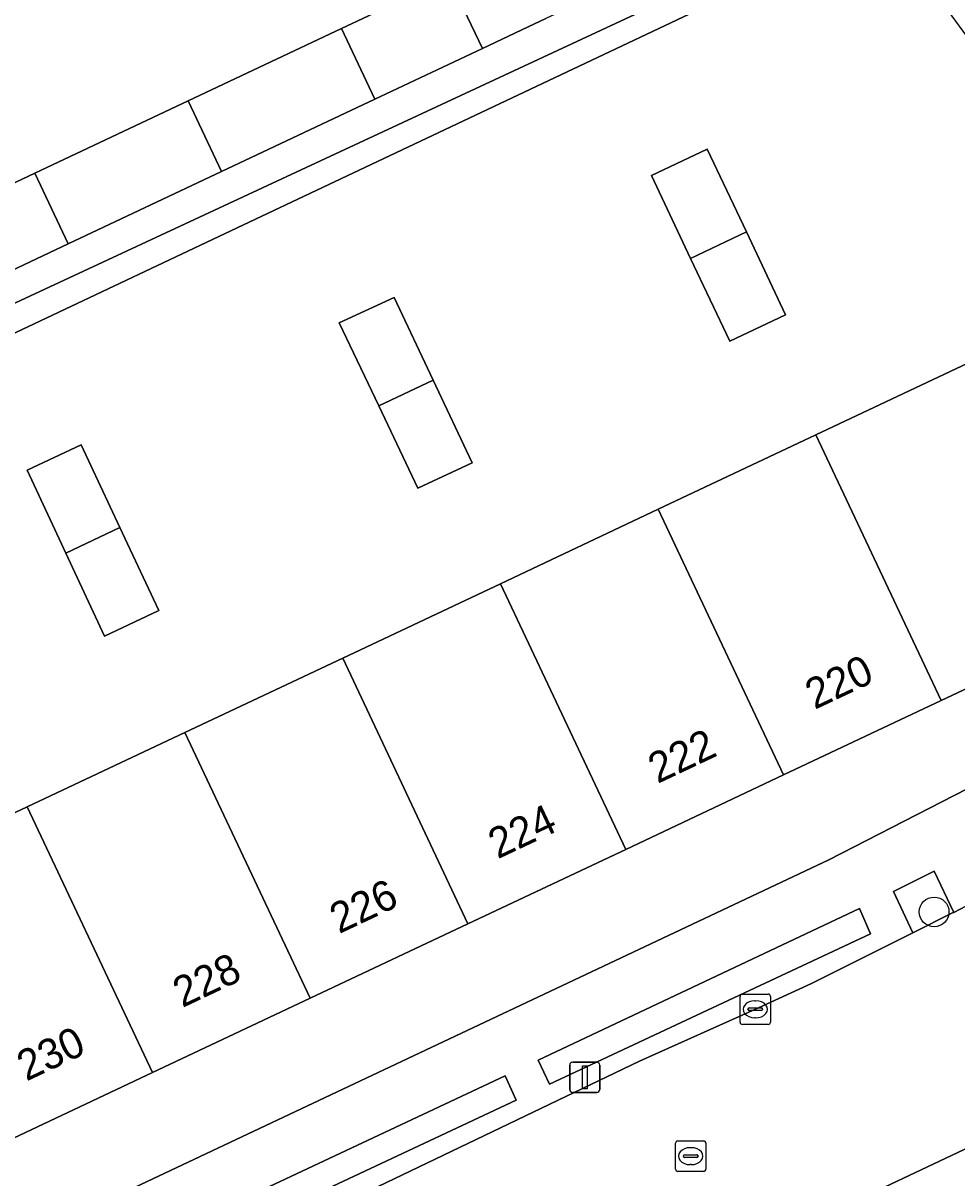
# Model space of a CAD drawing. Extents: x 159039 to 160102, y 381214 to 382524.
# Drawn here: x 159239.29 to 159270.04, y 381343.22 to 381381.25 of the extents above; entities that cross this region are included whole.
import ezdxf

# ---------------------------------------------------------------- set-up
doc = ezdxf.new("R2010")
doc.units = 0
for name, color, linetype in [('IMGEO_Berm_groen', 7, 'Continuous'), ('IMGEO_Boom', 7, 'Continuous'), ('IMGEO_Erf', 7, 'Continuous'), ('IMGEO_Groenvoorziening', 7, 'Continuous'), ('IMGEO_Kolk', 7, 'Continuous'), ('IMGEO_Lichtmast', 7, 'Continuous'), ('IMGEO_Pand', 7, 'Continuous'), ('IMGEO_Pand_nummerreeks', 7, 'Continuous'), ('IMGEO_Rijbaan_lokaal_gesloten', 7, 'Continuous'), ('IMGEO_Rioolput', 7, 'Continuous'), ('IMGEO_Voetpad_open', 7, 'Continuous')]:
    doc.layers.add(name, color=color, linetype=linetype)

msp = doc.modelspace()

# ---------------------------------------------------------------- linework, layer by layer
at = {"layer": 'IMGEO_Berm_groen'}
msp.add_lwpolyline([(159281.002, 381349.59), (159276.504, 381347.102), (159259.828, 381339.216), (159244.02, 381331.744), (159232.721, 381326.338), (159225.919, 381323.116), (159208.328, 381314.79), (159207.455, 381314.381), (159205.625, 381313.592), (159218.979, 381296.165)], dxfattribs=at)
at = {"layer": 'IMGEO_Boom'}
msp.add_circle((159269.29, 381351.983), 0.489, dxfattribs=at)
at = {"layer": 'IMGEO_Erf'}
for points in [[(159280.348, 381367.214), (159267.618, 381384.57), (159261.829, 381381.834), (159246.942, 381374.798), (159231.151, 381367.335), (159231.408, 381366.79), (159210.414, 381356.868), (159187.998, 381346.282), (159194.413, 381332.419), (159197.436, 381326.24)], [(159224.414, 381382.139), (159229.323, 381371.43), (159234.634, 381373.935), (159235.733, 381371.602), (159237.424, 381372.4), (159236.325, 381374.733), (159239.678, 381376.315), (159244.727, 381378.696), (159249.773, 381381.077), (159253.314, 381382.747), (159254.414, 381380.414), (159255.921, 381381.125), (159256.504, 381381.4)], [(159234.234, 381352.997), (159239.428, 381355.446), (159244.622, 381357.894), (159249.816, 381360.343), (159255.01, 381362.792), (159260.204, 381365.241), (159265.398, 381367.689), (159270.592, 381370.138), (159274.704, 381361.384), (159269.523, 381358.941), (159264.329, 381356.492), (159259.135, 381354.043), (159253.941, 381351.594), (159248.747, 381349.144), (159243.553, 381346.695), (159238.359, 381344.246)], [(159204.502, 381324.76), (159265.823, 381353.699), (159271.62, 381356.674), (159273.546, 381357.821), (159279.522, 381361.378)]]:
    msp.add_lwpolyline(points, dxfattribs=at)
for points in [[(159261.271, 381373.504), (159259.982, 381376.231), (159261.82, 381377.1), (159263.109, 381374.373), (159264.398, 381371.646), (159262.56, 381370.777)], [(159249.703, 381371.379), (159251.509, 381372.221), (159252.792, 381369.498), (159254.074, 381366.775), (159252.292, 381365.936), (159251, 381368.652)], [(159239.422, 381366.526), (159241.201, 381367.364), (159242.479, 381364.637), (159243.756, 381361.909), (159241.974, 381361.068), (159240.698, 381363.795), (159240.255, 381364.741)]]:
    msp.add_lwpolyline(points, close=True, dxfattribs=at)
at = {"layer": 'IMGEO_Groenvoorziening'}
for points in [[(159261.509, 381382.51), (159267.21, 381385.165), (159266.572, 381386.097), (159261.026, 381383.533), (159257.38, 381381.813), (159256.504, 381381.4), (159255.921, 381381.125), (159254.414, 381380.414), (159250.872, 381378.743), (159245.826, 381376.363), (159240.778, 381373.982), (159237.424, 381372.4), (159235.733, 381371.602), (159230.423, 381369.097), (159229.323, 381371.43), (159224.414, 381382.139), (159223.715, 381383.622), (159221.583, 381388.144), (159220.296, 381390.873), (159219.711, 381390.599), (159220.151, 381389.64), (159228.641, 381371.117), (159230.12, 381367.891)], [(159268.589, 381351.295), (159269.915, 381351.959), (159269.934, 381351.969), (159269.295, 381353.324), (159267.947, 381352.657)], [(159256.25, 381347.097), (159256.63, 381346.311), (159267.199, 381351.26), (159266.837, 381352.099)], [(159242.338, 381340.559), (159242.727, 381339.778), (159255.527, 381345.783), (159255.163, 381346.588)]]:
    msp.add_lwpolyline(points, close=True, dxfattribs=at)
at = {"layer": 'IMGEO_Kolk'}
for p, q in [((159262.9, 381348.35), (159262.9, 381349.202)), ((159262.975, 381349.276), (159263.827, 381349.276)), ((159263.388, 381349.056), (159263.413, 381349.056)), ((159263.901, 381349.202), (159263.901, 381348.35)), ((159263.159, 381348.77), (159263.159, 381348.782)), ((159263.597, 381348.733), (159263.199, 381348.733)), ((159263.202, 381348.819), (159263.6, 381348.819)), ((159263.643, 381348.782), (159263.643, 381348.77)), ((159263.411, 381348.496), (159263.386, 381348.496)), ((159263.827, 381348.276), (159262.975, 381348.276))]:
    msp.add_line(p, q, dxfattribs=at)
for points in [[(159262.9, 381348.35), (159262.9, 381349.202)], [(159262.975, 381349.276), (159263.827, 381349.276)], [(159263.901, 381349.202), (159263.901, 381348.35)], [(159263.827, 381348.276), (159262.975, 381348.276)]]:
    msp.add_lwpolyline(points, dxfattribs=at)
for centre, radius, start, end in [((159262.977, 381349.2), 0.0765, 91.552, 178.448), ((159262.977, 381349.2), 0.0765, 91.552, 178.448), ((159263.825, 381349.2), 0.0765, 1.552, 88.448), ((159263.825, 381349.2), 0.0765, 1.552, 88.448), ((159263.199, 381348.779), 0.0403, 85.8775, 175.7526), ((159263.196, 381348.769), 0.0366, 178.938, 274.7102), ((159263.6, 381348.776), 0.043, 264.8664, 352.4533), ((159263.604, 381348.781), 0.0386, 1.7309, 96.639), ((159262.977, 381348.352), 0.0765, 181.552, 268.448), ((159262.977, 381348.352), 0.0765, 181.552, 268.448), ((159263.825, 381348.352), 0.0765, 271.552, 358.448), ((159263.825, 381348.352), 0.0765, 271.552, 358.448)]:
    msp.add_arc(centre, radius, start, end, dxfattribs=at)
for centre, major_axis, ratio, start_param, end_param in [((159263.387, 381348.776), (-0.387, 0.002), 0.722429, 4.712389, 7.853982), ((159263.412, 381348.776), (-0.39, 0.002), 0.717154, 1.570796, 4.712389)]:
    msp.add_ellipse(centre, major_axis=major_axis, ratio=ratio, start_param=start_param, end_param=end_param, dxfattribs=at)
at = {"layer": 'IMGEO_Lichtmast'}
for p, q in [((159257.292, 381346.136), (159257.292, 381346.936)), ((159257.292, 381346.936), (159257.292, 381346.136)), ((159257.392, 381347.036), (159258.182, 381347.036)), ((159258.182, 381347.036), (159257.392, 381347.036)), ((159258.282, 381346.936), (159258.282, 381346.136)), ((159258.282, 381346.136), (159258.282, 381346.936)), ((159258.182, 381346.036), (159257.392, 381346.036)), ((159257.392, 381346.036), (159258.182, 381346.036))]:
    msp.add_line(p, q, dxfattribs=at)
msp.add_lwpolyline([(159257.712, 381346.911), (159257.862, 381346.911), (159257.862, 381346.161), (159257.712, 381346.161), (159257.712, 381346.911)], dxfattribs=at)
for centre, start, end in [((159257.392, 381346.936), 90, 180), ((159257.392, 381346.936), 90, 180), ((159258.182, 381346.936), 0, 90), ((159258.182, 381346.936), 360, 90), ((159257.392, 381346.136), 180, 270), ((159257.392, 381346.136), 180, 270), ((159258.182, 381346.136), 270, 0), ((159258.182, 381346.136), 270, 0)]:
    msp.add_arc(centre, 0.1, start, end, dxfattribs=at)
at = {"layer": 'IMGEO_Pand'}
for points in [[(159253.314, 381382.747), (159249.773, 381381.077), (159250.872, 381378.743), (159254.414, 381380.414)], [(159249.773, 381381.077), (159244.727, 381378.696), (159245.826, 381376.363), (159250.872, 381378.743)], [(159239.678, 381376.315), (159240.778, 381373.982), (159245.826, 381376.363), (159244.727, 381378.696)], [(159261.271, 381373.504), (159263.109, 381374.373), (159261.82, 381377.1), (159259.982, 381376.231)], [(159239.678, 381376.315), (159236.325, 381374.733), (159237.424, 381372.4), (159240.778, 381373.982)], [(159263.109, 381374.373), (159261.271, 381373.504), (159262.56, 381370.777), (159264.398, 381371.646)], [(159249.703, 381371.379), (159251, 381368.652), (159252.792, 381369.498), (159251.509, 381372.221)], [(159270.592, 381370.138), (159265.398, 381367.689), (159269.523, 381358.941), (159274.704, 381361.384)], [(159252.792, 381369.498), (159251, 381368.652), (159252.292, 381365.936), (159254.074, 381366.775)], [(159265.398, 381367.689), (159260.204, 381365.241), (159264.329, 381356.492), (159269.523, 381358.941)], [(159239.422, 381366.526), (159240.255, 381364.741), (159240.698, 381363.795), (159242.479, 381364.637), (159241.201, 381367.364)], [(159264.329, 381356.492), (159260.204, 381365.241), (159255.01, 381362.792), (159259.135, 381354.043)], [(159242.479, 381364.637), (159240.698, 381363.795), (159241.974, 381361.068), (159243.756, 381361.909)], [(159255.01, 381362.792), (159249.816, 381360.343), (159253.941, 381351.594), (159259.135, 381354.043)], [(159249.816, 381360.343), (159244.622, 381357.894), (159248.747, 381349.144), (159253.941, 381351.594)], [(159244.622, 381357.894), (159239.428, 381355.446), (159243.553, 381346.695), (159248.747, 381349.144)], [(159239.428, 381355.446), (159234.234, 381352.997), (159238.359, 381344.246), (159243.553, 381346.695)]]:
    msp.add_lwpolyline(points, close=True, dxfattribs=at)
at = {"layer": 'IMGEO_Rijbaan_lokaal_gesloten'}
for points in [[(159281.426, 381358.543), (159280.214, 381357.738), (159278.352, 381356.644), (159276.084, 381355.324), (159273.688, 381353.943), (159269.934, 381351.969), (159269.915, 381351.959), (159268.589, 381351.295), (159265.252, 381349.625), (159263.507, 381348.823), (159259.584, 381347.068), (159250.438, 381342.679), (159242.999, 381339.206), (159241.883, 381338.677), (159240.543, 381338.041), (159231.152, 381333.589), (159222.72, 381329.602), (159214.057, 381325.488), (159208.66, 381323.044), (159203.531, 381320.66)], [(159259.828, 381339.216), (159276.504, 381347.102), (159281.002, 381349.59)]]:
    msp.add_lwpolyline(points, dxfattribs=at)
at = {"layer": 'IMGEO_Rioolput'}
for p, q in [((159260.775, 381343.514), (159260.775, 381344.366)), ((159260.85, 381344.44), (159261.702, 381344.44)), ((159261.263, 381344.22), (159261.288, 381344.22)), ((159261.776, 381344.366), (159261.776, 381343.514)), ((159261.034, 381343.934), (159261.034, 381343.946)), ((159261.472, 381343.897), (159261.074, 381343.897)), ((159261.077, 381343.983), (159261.475, 381343.983)), ((159261.518, 381343.946), (159261.518, 381343.934)), ((159261.702, 381343.44), (159260.85, 381343.44)), ((159261.286, 381343.66), (159261.261, 381343.66))]:
    msp.add_line(p, q, dxfattribs=at)
for points in [[(159260.775, 381343.514), (159260.775, 381344.366)], [(159260.85, 381344.44), (159261.702, 381344.44)], [(159261.776, 381344.366), (159261.776, 381343.514)], [(159261.702, 381343.44), (159260.85, 381343.44)]]:
    msp.add_lwpolyline(points, dxfattribs=at)
for centre, radius, start, end in [((159260.852, 381344.364), 0.0765, 91.552, 178.448), ((159260.852, 381344.364), 0.0765, 91.552, 178.448), ((159261.7, 381344.364), 0.0765, 1.552, 88.448), ((159261.7, 381344.364), 0.0765, 1.552, 88.448), ((159261.074, 381343.943), 0.0403, 85.8775, 175.7526), ((159261.071, 381343.933), 0.0366, 178.938, 274.7102), ((159261.475, 381343.94), 0.043, 264.8664, 352.4533), ((159261.479, 381343.945), 0.0386, 1.7309, 96.639), ((159260.852, 381343.516), 0.0765, 181.552, 268.448), ((159260.852, 381343.516), 0.0765, 181.552, 268.448), ((159261.7, 381343.516), 0.0765, 271.552, 358.448), ((159261.7, 381343.516), 0.0765, 271.552, 358.448)]:
    msp.add_arc(centre, radius, start, end, dxfattribs=at)
for centre, major_axis, ratio, start_param, end_param in [((159261.262, 381343.94), (-0.387, 0.002), 0.722429, 4.712389, 7.853982), ((159261.287, 381343.94), (-0.39, 0.002), 0.717154, 1.570796, 4.712389)]:
    msp.add_ellipse(centre, major_axis=major_axis, ratio=ratio, start_param=start_param, end_param=end_param, dxfattribs=at)
at = {"layer": 'IMGEO_Voetpad_open'}
for points in [[(159261.509, 381382.51), (159230.12, 381367.891), (159228.641, 381371.117), (159220.151, 381389.64)], [(159187.998, 381346.282), (159210.414, 381356.868), (159231.408, 381366.79), (159231.151, 381367.335), (159246.942, 381374.798), (159261.829, 381381.834)], [(159284.717, 381364.428), (159279.522, 381361.378), (159273.546, 381357.821), (159271.62, 381356.674), (159265.823, 381353.699), (159204.502, 381324.76)], [(159250.438, 381342.679), (159259.584, 381347.068), (159263.507, 381348.823), (159265.252, 381349.625), (159268.589, 381351.295), (159267.947, 381352.657), (159269.295, 381353.324), (159269.934, 381351.969), (159273.688, 381353.943), (159276.084, 381355.324), (159278.352, 381356.644), (159280.214, 381357.738), (159281.426, 381358.543)]]:
    msp.add_lwpolyline(points, dxfattribs=at)
for points in [[(159256.25, 381347.097), (159266.837, 381352.099), (159267.199, 381351.26), (159256.63, 381346.311)], [(159242.338, 381340.559), (159255.163, 381346.588), (159255.527, 381345.783), (159242.727, 381339.778)]]:
    msp.add_lwpolyline(points, close=True, dxfattribs=at)

# ---------------------------------------------------------------- texts
at = {"layer": 'IMGEO_Pand_nummerreeks'}
for s, p in [('220', (159265.356, 381358.634)), ('222', (159260.182, 381356.195)), ('224', (159254.919, 381353.713)), ('226', (159249.698, 381351.251)), ('228', (159244.534, 381348.816)), ('230', (159239.399, 381346.395))]:
    msp.add_text(s, height=1, rotation=25.2458, dxfattribs=at).set_placement(p)

doc.saveas('drawing.dxf')
